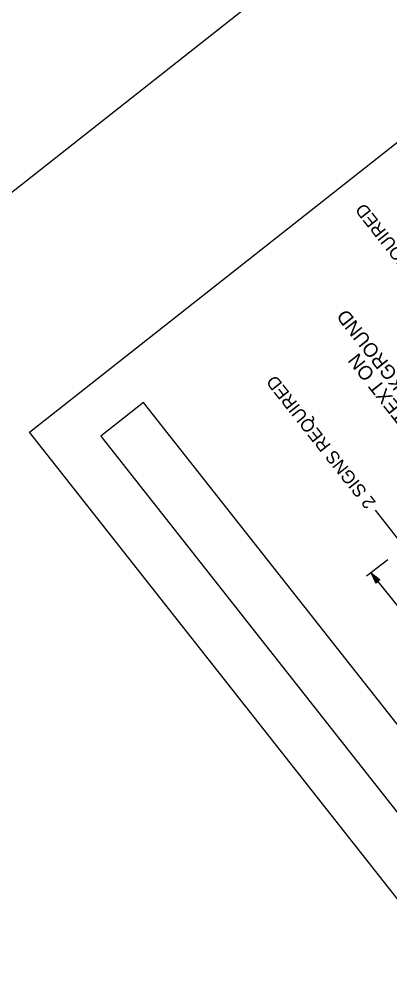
# Model space of a CAD drawing. Extents: x 671946 to 673995, y 1673066 to 1674936.
# Drawn here: x 672488.2 to 672609.4, y 1673451.7 to 1673764.1 of the extents above; entities that cross this region are included whole.
import ezdxf

# ---------------------------------------------------------------- set-up
doc = ezdxf.new("R2010")
doc.units = 0
doc.layers.add('C-ANNO-SYMB', color=7, linetype='Continuous')
doc.layers.add('Level 1', color=7, linetype='Continuous')

msp = doc.modelspace()

# ---------------------------------------------------------------- linework, layer by layer
at = {"layer": 'C-ANNO-SYMB'}
msp.add_lwpolyline([(672649.57, 1673485.71), (672528.92, 1673638.76), (672514.94, 1673627.74), (672635.59, 1673474.69)], close=True, dxfattribs=at)
at = {"layer": 'Level 1'}
for p, q in [((672645.37, 1673833.17), (672451.3, 1673680.17)), ((672491.61, 1673629.03), (672685.68, 1673782.02)), ((672631.4, 1673451.71), (672491.61, 1673629.03)), ((672614.33, 1673591.36), (672604.67, 1673603.61)), ((672608.73, 1673587.4), (672601.83, 1673581.96)), ((672614.06, 1673569.74), (672603.27, 1673583.1)), ((672604.98, 1673579.64), (672603.27, 1673583.1)), ((672603.27, 1673583.1), (672606.18, 1673580.78)), ((672603.63, 1673582.68), (672603.51, 1673582.88)), ((672603.51, 1673582.88), (672606.03, 1673580.8)), ((672604.96, 1673580), (672603.54, 1673582.84)), ((672603.54, 1673582.84), (672603.57, 1673582.63)), ((672603.57, 1673582.63), (672604, 1673581.83)), ((672604.93, 1673579.83), (672603.63, 1673582.68)), ((672604, 1673581.83), (672603.79, 1673582.53)), ((672603.79, 1673582.53), (672605.87, 1673580.8)), ((672605.04, 1673580.12), (672603.89, 1673582.31)), ((672603.89, 1673582.31), (672605.6, 1673580.76)), ((672605.04, 1673580.12), (672604.01, 1673582.24)), ((672604.01, 1673582.24), (672605.73, 1673580.8)), ((672604.61, 1673581.51), (672604.26, 1673581.87)), ((672604.26, 1673581.87), (672604.47, 1673581.44)), ((672605.09, 1673580.3), (672604.35, 1673581.81)), ((672604.35, 1673581.81), (672605.46, 1673580.81)), ((672604.71, 1673581.26), (672604.61, 1673581.51)), ((672605.13, 1673580.46), (672604.62, 1673581.42)), ((672604.62, 1673581.42), (672605.33, 1673580.85)), ((672605.47, 1673580.75), (672604.71, 1673581.26)), ((672605.18, 1673580.57), (672604.91, 1673581.08)), ((672604.91, 1673581.08), (672605.25, 1673580.82)), ((672605.11, 1673580.14), (672604.93, 1673579.83)), ((672605.06, 1673580), (672604.96, 1673580)), ((672605.47, 1673580.46), (672605, 1673579.78)), ((672605.73, 1673580.8), (672605.04, 1673580.12)), ((672605.61, 1673580.66), (672605.04, 1673580.12)), ((672605.6, 1673580.76), (672605.09, 1673580.3)), ((672605.42, 1673580.39), (672605.11, 1673580.14)), ((672605.46, 1673580.81), (672605.13, 1673580.46)), ((672605.33, 1673580.85), (672605.18, 1673580.57)), ((672605.25, 1673580.82), (672605.19, 1673580.73)), ((672605.19, 1673580.73), (672605.2, 1673580.38)), ((672605.2, 1673580.38), (672605.47, 1673580.75)), ((672606.18, 1673580.78), (672605.42, 1673580.39)), ((672606.03, 1673580.8), (672605.47, 1673580.46)), ((672605.87, 1673580.8), (672605.61, 1673580.66))]:
    msp.add_line(p, q, dxfattribs=at)

# ---------------------------------------------------------------- texts
for s, height, p in [('1 SIGN REQUIRED', 4.2, (672631.79, 1673665.29)), ('BLUE BACKGROUND', 4.5747, (672633.35, 1673621.32)), ('WHITE TEXT ON', 4.5747, (672628.68, 1673617.63)), ('2 SIGNS REQUIRED', 4.2, (672605.03, 1673606.15))]:
    msp.add_text(s, height=height, rotation=128.2505, dxfattribs=at).set_placement(p)

doc.saveas('drawing.dxf')
